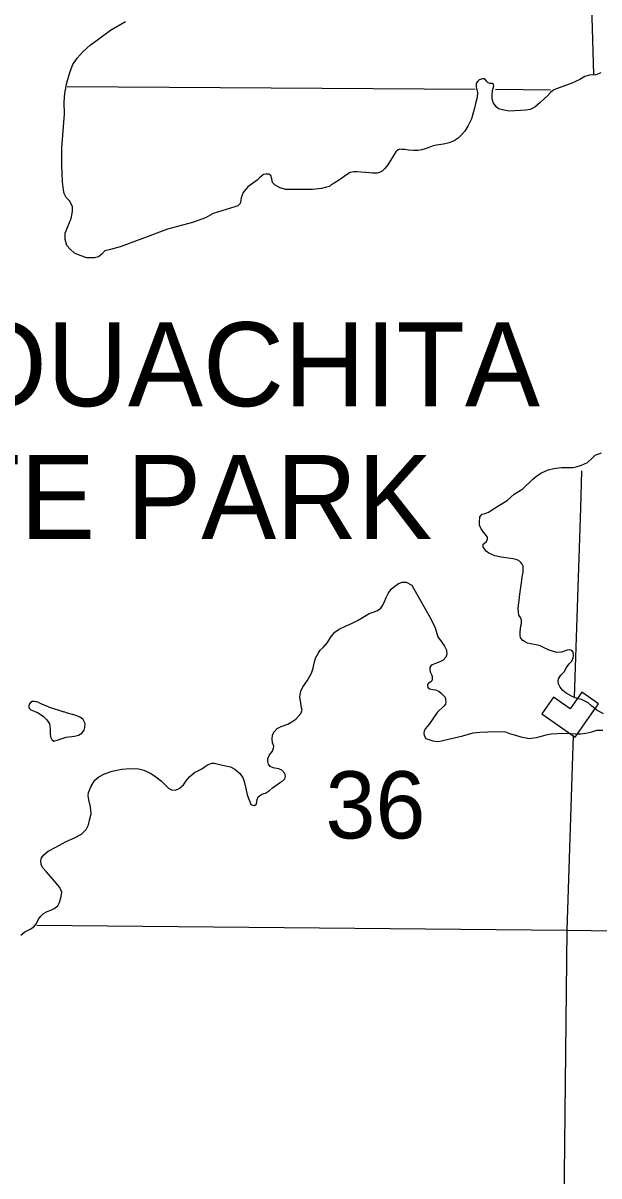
# Model space of a CAD drawing. Extents: x -3711 to 825, y -151 to 1050.
# Drawn here: x -2988.5 to -2947.9, y 243.7 to 325 of the extents above; entities that cross this region are included whole.
import ezdxf

# ---------------------------------------------------------------- set-up
doc = ezdxf.new("R2010")
doc.units = 0
for name, color, linetype in [('Level 4', 7, 'Continuous'), ('Level 5', 7, 'Continuous'), ('Level 57', 7, 'Continuous'), ('Level 7', 7, 'Continuous'), ('Level 9', 7, 'Continuous')]:
    doc.layers.add(name, color=color, linetype=linetype)

msp = doc.modelspace()

# ---------------------------------------------------------------- linework, layer by layer
at = {"layer": 'Level 4'}
for points in [[(-2948.848, 340.768), (-2948.298, 321.353)], [(-2949.128, 293.41), (-2949.212, 290.788), (-2949.644, 277.464)], [(-2949.731, 274.759), (-2950.175, 261.044)], [(-2987.506, 261.386), (-2950.175, 261.044)], [(-2950.175, 261.044), (-2950.506, 230.924), (-2950.697, 211.501)], [(-2950.175, 261.044), (-2924.417, 260.676)]]:
    msp.add_lwpolyline(points, dxfattribs=at)
at = {"layer": 'Level 5'}
for points in [[(-2985.382, 320.506), (-2956.628, 320.309)], [(-2955.203, 320.3), (-2951.333, 320.273)]]:
    msp.add_lwpolyline(points, dxfattribs=at)
at = {"layer": 'Level 57'}
msp.add_lwpolyline([(-2947.945, 276.995), (-2949.119, 277.809), (-2949.934, 276.635), (-2951.108, 277.449), (-2951.922, 276.275), (-2949.574, 274.646)], close=True, dxfattribs=at)
at = {"layer": 'Level 9'}
msp.add_line((-2986.685, 276.776), (-2985.62, 276.42), dxfattribs=at)
for points in [[(-2985.158, 321.56), (-2984.963, 322.04), (-2984.663, 322.49), (-2984.243, 322.955), (-2983.749, 323.42), (-2983.149, 323.855), (-2982.309, 324.47), (-2981.275, 325.071)], [(-2956.583, 319.398), (-2956.687, 318.977), (-2956.777, 318.632), (-2956.882, 318.212), (-2957.137, 317.702), (-2957.362, 317.357), (-2957.602, 317.102), (-2957.827, 316.847), (-2958.097, 316.667), (-2958.472, 316.532), (-2958.861, 316.442), (-2959.356, 316.367), (-2959.581, 316.322), (-2959.821, 316.217), (-2960.151, 316.097), (-2960.376, 316.037), (-2960.645, 315.992), (-2960.975, 315.977), (-2961.32, 316.007), (-2961.605, 316.052), (-2961.785, 316.067), (-2961.935, 316.082), (-2962.055, 316.037), (-2962.22, 315.902), (-2962.774, 314.986), (-2962.984, 314.716), (-2963.179, 314.536), (-2963.359, 314.431), (-2963.539, 314.386), (-2963.854, 314.386), (-2964.079, 314.416), (-2964.349, 314.446), (-2964.678, 314.461), (-2964.963, 314.491), (-2965.173, 314.491), (-2965.443, 314.446), (-2965.698, 314.266), (-2966.118, 313.966), (-2966.552, 313.696), (-2966.777, 313.576), (-2966.882, 313.456), (-2967.107, 313.396), (-2967.452, 313.306), (-2968.082, 313.231), (-2968.816, 313.231), (-2969.431, 313.231), (-2969.986, 313.231), (-2970.375, 313.366), (-2970.72, 313.546), (-2970.9, 313.741), (-2970.96, 313.996), (-2971.02, 314.221), (-2971.17, 314.326), (-2971.38, 314.326), (-2971.545, 314.296), (-2971.665, 314.191), (-2971.83, 314.056), (-2971.98, 313.906), (-2972.654, 313.426), (-2972.984, 313.021), (-2973.104, 312.661), (-2973.134, 312.466), (-2973.194, 312.241), (-2973.344, 312.091), (-2973.569, 312.016), (-2974.468, 311.731), (-2975.098, 311.551), (-2975.623, 311.25), (-2976.552, 310.905), (-2978.306, 310.44), (-2980.12, 309.765), (-2981.635, 309.195), (-2982.309, 309.015), (-2982.729, 308.91), (-2982.939, 308.685), (-2983.164, 308.505), (-2983.449, 308.43), (-2983.989, 308.43), (-2984.468, 308.58), (-2984.858, 308.76), (-2985.173, 309.03), (-2985.398, 309.3), (-2985.518, 309.72), (-2985.518, 310.155), (-2985.338, 310.635), (-2985.098, 311.205), (-2985.008, 311.686), (-2985.008, 312.016), (-2985.188, 312.406), (-2985.443, 312.676), (-2985.578, 312.946), (-2985.638, 313.216), (-2985.713, 313.773), (-2985.758, 314.943), (-2985.758, 316.143), (-2985.683, 317.058), (-2985.563, 318.544), (-2985.578, 319.399), (-2985.533, 320.029), (-2985.398, 320.764), (-2985.158, 321.56)], [(-2947.767, 321.453), (-2948.127, 321.333), (-2948.577, 321.288), (-2948.906, 321.198), (-2949.251, 320.988), (-2949.866, 320.703), (-2950.526, 320.478), (-2951.095, 320.253), (-2951.32, 320.073), (-2951.515, 319.863), (-2952.055, 319.368), (-2952.43, 319.038), (-2952.745, 318.887), (-2953.059, 318.827), (-2953.434, 318.797), (-2953.839, 318.782), (-2954.199, 318.767), (-2954.619, 318.827), (-2954.978, 318.932), (-2955.158, 319.068), (-2955.368, 319.368), (-2955.428, 319.623), (-2955.428, 319.923), (-2955.398, 320.208), (-2955.353, 320.373), (-2955.308, 320.553), (-2955.338, 320.643), (-2955.428, 320.703), (-2955.593, 320.703), (-2955.713, 320.763), (-2955.818, 320.853), (-2955.893, 320.973), (-2955.998, 321.048), (-2956.118, 321.048), (-2956.358, 320.958), (-2956.448, 320.883), (-2956.568, 320.718), (-2956.553, 320.463), (-2956.463, 320.073), (-2956.493, 319.713), (-2956.583, 319.398)], [(-2949.143, 277.284), (-2949.578, 277.404), (-2949.848, 277.524), (-2950.208, 277.735), (-2950.463, 277.93), (-2950.643, 278.17), (-2950.763, 278.395), (-2950.778, 278.605), (-2950.763, 278.755), (-2950.583, 279.01), (-2950.358, 279.235), (-2950.193, 279.55), (-2949.998, 279.805), (-2949.818, 280), (-2949.728, 280.225), (-2949.698, 280.42), (-2949.713, 280.63), (-2949.818, 280.75), (-2949.953, 280.795), (-2950.148, 280.765), (-2950.553, 280.63), (-2950.867, 280.615), (-2951.407, 280.78), (-2951.767, 280.945), (-2952.052, 281.08), (-2952.337, 281.155), (-2952.727, 281.215), (-2952.951, 281.275), (-2953.161, 281.381), (-2953.281, 281.456), (-2953.446, 281.636), (-2953.461, 281.831), (-2953.461, 282.056), (-2953.401, 282.476), (-2953.356, 282.641), (-2953.356, 282.881), (-2953.431, 283.061), (-2953.551, 283.241), (-2953.581, 283.466), (-2953.611, 283.691), (-2953.581, 283.931), (-2953.521, 284.276), (-2953.476, 284.711), (-2953.371, 285.522), (-2953.311, 285.912), (-2953.236, 286.272), (-2953.236, 286.452), (-2953.251, 286.692), (-2953.311, 286.827), (-2953.401, 286.947), (-2953.506, 287.052), (-2953.671, 287.142), (-2953.956, 287.202), (-2954.301, 287.262), (-2954.795, 287.322), (-2955.245, 287.427), (-2955.665, 287.607), (-2955.845, 287.757), (-2956.055, 288.027), (-2956.055, 288.237), (-2955.845, 288.417), (-2955.77, 288.567), (-2955.77, 288.732), (-2955.89, 288.927), (-2956.04, 289.078), (-2956.205, 289.318), (-2956.325, 289.573), (-2956.325, 289.798), (-2956.295, 290.158), (-2956.13, 290.353), (-2955.92, 290.413), (-2955.695, 290.488), (-2955.545, 290.593), (-2955.035, 290.908), (-2954.376, 291.313), (-2953.881, 291.763), (-2953.266, 292.138), (-2952.577, 292.814), (-2952.277, 293.054), (-2951.947, 293.279), (-2951.497, 293.474), (-2951.092, 293.579), (-2950.553, 293.639), (-2950.118, 293.639), (-2949.713, 293.654), (-2949.518, 293.699), (-2949.128, 293.804), (-2948.709, 293.999), (-2948.409, 294.269), (-2948.169, 294.509), (-2947.734, 294.689)], [(-2978.738, 271.538), (-2978.438, 271.253), (-2978.229, 271.043), (-2978.034, 270.923), (-2977.749, 270.893), (-2977.494, 271.013), (-2977.179, 271.283), (-2976.999, 271.568), (-2976.744, 271.853), (-2976.399, 272.138), (-2976.16, 272.273), (-2975.875, 272.408), (-2975.71, 272.528), (-2975.44, 272.723), (-2975.185, 272.813), (-2975.02, 272.813), (-2974.825, 272.753), (-2974.42, 272.663), (-2973.866, 272.543), (-2973.551, 272.393), (-2973.221, 272.108), (-2972.996, 271.793), (-2972.906, 271.523), (-2972.786, 271.028), (-2972.681, 270.578), (-2972.531, 270.158), (-2972.426, 269.902), (-2972.322, 269.857), (-2972.187, 269.827), (-2972.037, 269.948), (-2971.992, 270.233), (-2971.917, 270.443), (-2971.662, 270.623), (-2971.392, 270.698), (-2971.122, 270.878), (-2970.912, 271.058), (-2970.343, 271.463), (-2970.178, 271.568), (-2970.028, 271.703), (-2969.983, 271.898), (-2970.043, 272.078), (-2970.238, 272.303), (-2970.462, 272.408), (-2970.732, 272.453), (-2970.867, 272.483), (-2971.077, 272.573), (-2971.182, 272.738), (-2971.227, 272.918), (-2971.227, 273.143), (-2971.107, 273.398), (-2970.897, 273.653), (-2970.837, 273.864), (-2970.822, 274.014), (-2970.897, 274.239), (-2970.942, 274.509), (-2970.912, 274.779), (-2970.807, 274.989), (-2970.567, 275.244), (-2970.298, 275.379), (-2969.818, 275.559), (-2969.548, 275.709), (-2969.263, 275.904), (-2968.903, 276.309), (-2968.828, 276.534), (-2968.858, 276.714), (-2968.918, 277.029), (-2968.993, 277.479), (-2968.918, 277.9), (-2968.738, 278.2), (-2968.454, 278.62), (-2968.169, 279.145), (-2968.049, 279.49), (-2967.974, 279.85), (-2967.869, 280.195), (-2967.689, 280.525), (-2967.539, 280.765), (-2967.344, 280.96), (-2967.029, 281.32), (-2966.774, 281.741), (-2966.505, 282.041), (-2966.22, 282.251), (-2965.725, 282.476), (-2965.335, 282.641), (-2964.915, 282.866), (-2964.511, 283.106), (-2964.106, 283.346), (-2963.806, 283.451), (-2963.506, 283.556), (-2963.281, 283.736), (-2963.131, 283.946), (-2963.011, 284.201), (-2962.891, 284.486), (-2962.756, 284.771), (-2962.547, 285.071), (-2962.292, 285.282), (-2962.022, 285.462), (-2961.752, 285.552), (-2961.482, 285.552), (-2961.092, 285.357), (-2960.942, 285.101), (-2960.553, 284.396)], [(-2960.553, 284.396), (-2959.743, 282.971), (-2959.458, 282.356), (-2959.248, 281.711), (-2959.008, 281.351), (-2958.798, 281.05), (-2958.649, 280.78), (-2958.634, 280.495), (-2958.694, 280.285), (-2958.873, 280.075), (-2959.113, 279.94), (-2959.413, 279.82), (-2959.653, 279.745), (-2959.758, 279.67), (-2959.818, 279.55), (-2959.818, 279.415), (-2959.803, 279.235), (-2959.698, 279.055), (-2959.668, 278.92), (-2959.668, 278.725), (-2959.683, 278.605), (-2959.743, 278.53), (-2959.863, 278.47), (-2959.923, 278.44), (-2959.998, 278.35), (-2959.998, 278.26), (-2959.938, 278.125), (-2959.833, 278.05), (-2959.623, 278.005), (-2959.413, 277.975), (-2959.188, 277.87), (-2959.008, 277.72), (-2958.753, 277.464), (-2958.708, 277.299), (-2958.694, 277.104), (-2958.723, 276.954), (-2958.843, 276.819), (-2959.308, 276.369), (-2959.608, 275.934), (-2959.788, 275.649), (-2959.998, 275.424), (-2960.163, 275.229), (-2960.223, 275.064), (-2960.253, 274.914), (-2960.223, 274.749), (-2960.103, 274.554), (-2959.833, 274.449), (-2959.608, 274.374), (-2959.248, 274.329), (-2958.993, 274.374), (-2958.424, 274.509), (-2957.509, 274.734), (-2956.759, 274.944), (-2956.295, 274.989), (-2955.74, 275.004), (-2954.96, 275.034), (-2954.481, 275.004), (-2954.151, 274.884), (-2953.791, 274.779), (-2953.401, 274.659), (-2953.041, 274.584), (-2952.846, 274.554), (-2952.307, 274.614), (-2951.962, 274.719), (-2951.632, 274.809), (-2951.272, 274.869), (-2950.853, 274.899), (-2950.493, 274.914), (-2949.893, 274.899), (-2949.548, 274.869), (-2949.173, 274.869), (-2948.829, 274.914), (-2948.409, 275.004), (-2948.049, 275.124), (-2947.644, 275.139)], [(-2986.685, 276.776), (-2987.106, 276.941), (-2987.403, 277.071), (-2987.514, 277.127), (-2987.7, 277.145), (-2987.849, 277.145), (-2987.96, 277.09), (-2988.053, 276.941), (-2988.071, 276.829), (-2988.071, 276.699), (-2987.941, 276.569), (-2987.7, 276.476), (-2987.421, 276.346), (-2987.05, 276.105), (-2986.809, 275.863), (-2986.623, 275.584), (-2986.567, 275.212), (-2986.567, 274.897), (-2986.549, 274.655), (-2986.456, 274.469), (-2986.307, 274.358), (-2986.159, 274.395), (-2985.453, 274.636), (-2984.859, 274.711), (-2984.58, 274.785), (-2984.339, 274.915), (-2984.172, 275.12), (-2984.134, 275.324), (-2984.116, 275.603), (-2984.246, 275.882), (-2984.432, 276.03), (-2984.747, 276.16), (-2984.989, 276.235), (-2985.342, 276.328), (-2985.62, 276.42)], [(-2947.599, 276.294), (-2948.049, 276.549), (-2948.424, 276.849), (-2948.664, 277.059), (-2948.904, 277.179), (-2949.143, 277.284)], [(-2988.633, 260.69), (-2988.348, 260.915), (-2987.974, 261.11), (-2987.719, 261.26), (-2987.524, 261.5), (-2987.389, 261.8), (-2987.224, 262.025), (-2987.044, 262.22), (-2986.789, 262.355), (-2986.519, 262.446), (-2986.279, 262.566), (-2986.04, 262.761), (-2985.92, 262.986), (-2985.8, 263.406), (-2985.755, 263.706), (-2985.89, 264.036), (-2986.264, 264.486), (-2986.819, 265.146), (-2987.119, 265.446), (-2987.209, 265.671), (-2987.239, 265.911), (-2987.179, 266.136), (-2987.029, 266.347), (-2986.714, 266.602), (-2986.174, 266.887), (-2985.455, 267.277), (-2984.855, 267.532), (-2984.375, 267.802), (-2984.046, 268.132), (-2983.866, 268.462), (-2983.791, 268.777), (-2983.686, 269.227), (-2983.731, 269.722), (-2983.851, 270.218), (-2983.896, 270.503), (-2983.866, 270.743), (-2983.671, 271.178), (-2983.416, 271.598), (-2983.146, 271.838), (-2982.741, 272.048), (-2982.201, 272.243), (-2981.512, 272.393), (-2980.942, 272.423), (-2980.357, 272.408), (-2979.968, 272.303), (-2979.443, 272.063), (-2979.128, 271.853), (-2978.738, 271.538)]]:
    msp.add_lwpolyline(points, dxfattribs=at)

# ---------------------------------------------------------------- texts
at = {"layer": 'Level 5'}
msp.add_text('36', height=4.7343, dxfattribs=at).set_placement((-2967.174, 267.501))
at = {"layer": 'Level 7'}
for s, height, p in [('LAKE OUACHITA', 5.91788, (-3015.392, 297.966)), ('STATE PARK', 5.9179, (-3008.903, 288.608))]:
    msp.add_text(s, height=height, dxfattribs=at).set_placement(p)

doc.saveas('drawing.dxf')
